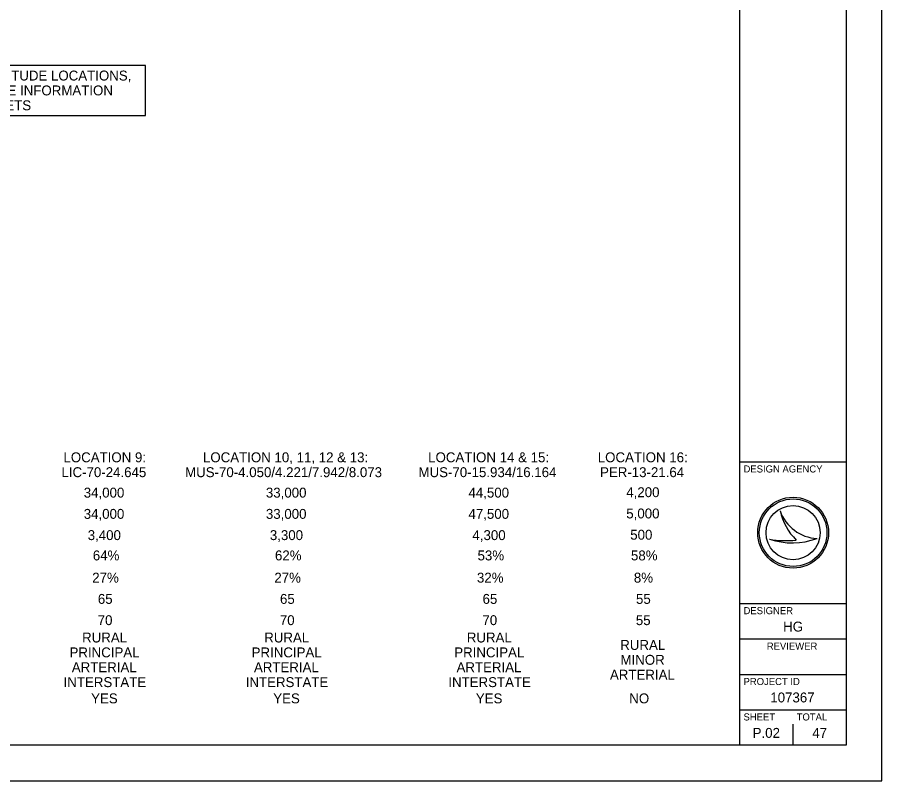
# Model space of a CAD drawing. Extents: x 1761803 to 2441803, y 509895 to 949895.
# Drawn here: x 2197858 to 2441803, y 509895 to 725372 of the extents above; entities that cross this region are included whole.
import ezdxf

# ---------------------------------------------------------------- set-up
doc = ezdxf.new("R2010")
doc.units = 0
for name, color, linetype in [('Default', 7, 'Continuous'), ('GM_X_Major_Lake', 7, 'Continuous'), ('GM_X_State_Location', 7, 'Continuous'), ('GM_X_Township_Road_Text', 7, 'Continuous'), ('GM_X_Township_ROW', 7, 'Continuous'), ('GM_X_Township_Subdivision', 7, 'Continuous')]:
    doc.layers.add(name, color=color, linetype=linetype)

msp = doc.modelspace()

# ---------------------------------------------------------------- linework, layer by layer
at = {"layer": 'Default'}
msp.add_lwpolyline([(2146236, 697679), (2234016, 697679), (2234016, 711775), (2146236, 711775)], close=True, dxfattribs=at)
at = {"layer": 'GM_X_Township_Road_Text'}
msp.add_lwpolyline([(1761803, 509895), (2441803, 509895), (2441803, 949895), (1761803, 949895)], close=True, dxfattribs=at)
at = {"layer": 'GM_X_Township_ROW'}
for p, q in [((2413152, 586086), (2413153, 586086)), ((2416803, 579895), (2416803, 579895)), ((2423549, 578265), (2423550, 578265)), ((2410147, 578085), (2410147, 578085)), ((2416803, 519895), (2416803, 525895)), ((2409303, 523395), (2409303, 523395))]:
    msp.add_line(p, q, dxfattribs=at)
for radius in [10000, 9536, 9536, 7644]:
    msp.add_circle((2416803, 579895), radius, dxfattribs=at)
for centre, radius, start, end in [((2424122, 589848), 11597, 198.92567, 198.93195), ((2428737, 589296), 15912, 191.63793, 191.64215), ((2424122, 589848), 11597, 198.93195, 267.16574), ((2428737, 589296), 15912, 191.64215, 226.09467), ((2416592, 597295), 20262, 251.45764, 290.08324), ((2414763, 602982), 25321, 259.49639, 259.49952), ((2416592, 597295), 20262, 251.45274, 251.45764), ((2414763, 602982), 25321, 259.49952, 276.66723)]:
    msp.add_arc(centre, radius, start, end, dxfattribs=at)
at = {"layer": 'GM_X_Township_Subdivision'}
for p, q in [((2401803, 519895), (2401803, 939895)), ((2401803, 599895), (2431803, 599895)), ((2401803, 559895), (2431803, 559895)), ((2401803, 549895), (2431803, 549895)), ((2401803, 539895), (2431803, 539895)), ((2401803, 529895), (2431803, 529895))]:
    msp.add_line(p, q, dxfattribs=at)
msp.add_lwpolyline([(1791803, 939895), (2431803, 939895), (2431803, 519895), (1791803, 519895)], close=True, dxfattribs=at)

# ---------------------------------------------------------------- texts
at = {"layer": 'GM_X_Major_Lake'}
for s, p in [('LOCATION 9:', (2210890, 599776)), ('LOCATION 10, 11, 12 & 13:', (2250261, 599776)), ('LOCATION 14 & 15:', (2313809, 599776)), ('LOCATION 16:', (2361673, 599776)), ('LIC-70-24.645', (2210326, 595576)), ('MUS-70-4.050/4.221/7.942/8.073', (2245213, 595576)), ('MUS-70-15.934/16.164', (2311088, 595576)), ('PER-13-21.64', (2362321, 595576)), ('34,000', (2216615, 589808)), ('33,000', (2268016, 589808)), ('44,500', (2325187, 589808)), ('4,200', (2369720, 589925)), ('34,000', (2216615, 583808)), ('33,000', (2268016, 583808)), ('47,500', (2325187, 583808)), ('5,000', (2369720, 583925)), ('3,400', (2217733, 577808)), ('3,300', (2269133, 577808)), ('4,300', (2326304, 577808)), ('500', (2370837, 577925)), ('64%', (2219174, 572078)), ('62%', (2270575, 572078)), ('53%', (2327746, 572078)), ('58%', (2371044, 572078)), ('27%', (2219006, 565808)), ('27%', (2270407, 565808)), ('32%', (2327578, 565808)), ('8%', (2371859, 565808)), ('65', (2220592, 559808)), ('65', (2271992, 559808)), ('65', (2329164, 559808)), ('55', (2372462, 559808)), ('70', (2220550, 553808)), ('70', (2271950, 553808)), ('70', (2329122, 553808)), ('55', (2372420, 553808)), ('RURAL', (2216147, 548916)), ('RURAL', (2267548, 548916)), ('RURAL', (2324719, 548916)), ('RURAL', (2368017, 546816)), ('PRINCIPAL', (2212596, 544716)), ('PRINCIPAL', (2263996, 544716)), ('PRINCIPAL', (2321168, 544716)), ('MINOR', (2368086, 542616)), ('ARTERIAL', (2213247, 540516)), ('ARTERIAL', (2264647, 540516)), ('ARTERIAL', (2321819, 540516)), ('INTERSTATE', (2210929, 536316)), ('INTERSTATE', (2262330, 536316)), ('INTERSTATE', (2319501, 536316)), ('ARTERIAL', (2365117, 538416)), ('YES', (2218696, 531732)), ('YES', (2270097, 531732)), ('YES', (2327268, 531732)), ('NO', (2370567, 531732))]:
    msp.add_text(s, height=2800, dxfattribs=at).set_placement(p)
at = {"layer": 'GM_X_State_Location'}
for s, p in [('FOR LATITUDE AND LONGITUDE LOCATIONS,', (2147461, 707526)), ('SEE EXISTING STRUCTURE INFORMATION', (2147461, 703326)), ('ON CULVERT DETAIL SHEETS', (2147461, 699126))]:
    msp.add_text(s, height=2800, dxfattribs=at).set_placement(p)
at = {"layer": 'GM_X_Township_ROW'}
for s, height, p in [('DESIGN AGENCY', 2000, (2402803, 596895)), ('DESIGNER', 2000, (2402803, 556895)), ('HG', 2800, (2413992, 551995)), ('REVIEWER', 2000, (2409369, 546895)), ('PROJECT ID', 2000, (2402803, 536895)), ('107367', 2800, (2410368, 531995)), ('SHEET', 2000, (2402803, 526895)), ('TOTAL', 2000, (2417803, 526895)), ('P.02', 2800, (2405384, 521995)), ('47', 2800, (2422217, 521995))]:
    msp.add_text(s, height=height, dxfattribs=at).set_placement(p)

doc.saveas('drawing.dxf')
